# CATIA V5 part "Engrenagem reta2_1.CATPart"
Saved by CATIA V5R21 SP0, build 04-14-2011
Part number: Engrenagem reta2_1
Definition: Engrenagem reta2_1
Nomenclature: Engrenagem reta21
Source: Unknown
Bounding box of the stored display mesh (mm): x -2.388 to 2.388, y -2.386 to 2.388, z 0 to 0.5
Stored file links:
  C:\Users\beatr\OneDrive\Documents\UNB\2026_1\Pi1\Componentes eletronicos\Engrenagem reta2_1.CATPart
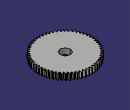
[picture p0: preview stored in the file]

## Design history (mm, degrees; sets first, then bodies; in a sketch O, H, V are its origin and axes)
Body1 "Solid1" (main body)
  Solid1: solid without history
